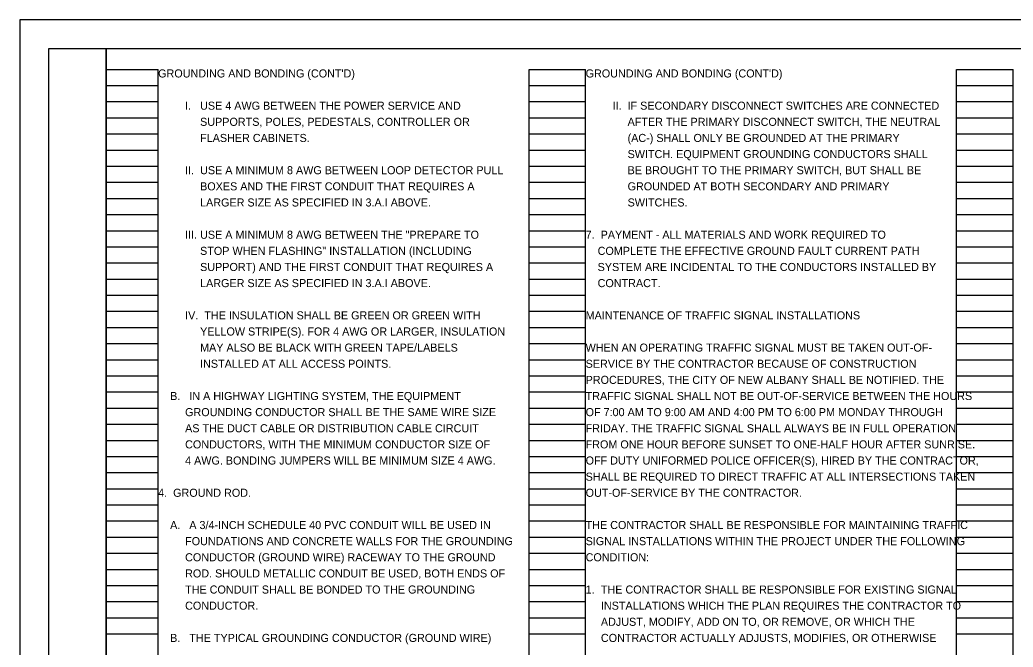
# Model space of a CAD drawing. Extents: x 0 to 34, y 0 to 22.
# Drawn here: x 0 to 17.24, y 11.11 to 22 of the extents above; entities that cross this region are included whole.
import ezdxf

# ---------------------------------------------------------------- set-up
doc = ezdxf.new("R2010")
doc.units = 0
for name, color, linetype in [('SH_Border', 7, 'Continuous'), ('SH_Cut_Line', 7, 'Continuous'), ('SH_Data', 7, 'Continuous'), ('SH_Text', 7, 'Continuous')]:
    doc.layers.add(name, color=color, linetype=linetype)

msp = doc.modelspace()

# ---------------------------------------------------------------- linework, layer by layer
at = {"layer": 'SH_Border'}
for points in [[(0.5, 21.5), (1.5, 21.5), (1.5, 0.5), (0.5, 0.5)], [(1.5, 21.5), (33.5, 21.5), (33.5, 0.5), (1.5, 0.5)]]:
    msp.add_lwpolyline(points, close=True, dxfattribs=at)
at = {"layer": 'SH_Cut_Line'}
msp.add_lwpolyline([(0, 0), (34, 0), (34, 22), (0, 22)], close=True, dxfattribs=at)
at = {"layer": 'SH_Data'}
for p, q in [((1.5, 0.98), (1.5, 21.14)), ((1.5, 21.14), (2.4, 21.14)), ((2.4, 0.98), (2.4, 21.14)), ((8.84, 0.98), (8.84, 21.14)), ((8.84, 21.14), (9.82, 21.14)), ((9.82, 0.98), (9.82, 21.14)), ((16.26, 0.98), (16.26, 21.14)), ((16.26, 21.14), (17.24, 21.14)), ((17.24, 0.98), (17.24, 21.14)), ((1.5, 20.86), (2.4, 20.86)), ((8.84, 20.86), (9.82, 20.86)), ((16.26, 20.86), (17.24, 20.86)), ((1.5, 20.58), (2.4, 20.58)), ((8.84, 20.58), (9.82, 20.58)), ((16.26, 20.58), (17.24, 20.58)), ((1.5, 20.3), (2.4, 20.3)), ((8.84, 20.3), (9.82, 20.3)), ((16.26, 20.3), (17.24, 20.3)), ((1.5, 20.02), (2.4, 20.02)), ((8.84, 20.02), (9.82, 20.02)), ((16.26, 20.02), (17.24, 20.02)), ((1.5, 19.74), (2.4, 19.74)), ((8.84, 19.74), (9.82, 19.74)), ((16.26, 19.74), (17.24, 19.74)), ((1.5, 19.46), (2.4, 19.46)), ((8.84, 19.46), (9.82, 19.46)), ((16.26, 19.46), (17.24, 19.46)), ((1.5, 19.18), (2.4, 19.18)), ((8.84, 19.18), (9.82, 19.18)), ((16.26, 19.18), (17.24, 19.18)), ((1.5, 18.9), (2.4, 18.9)), ((8.84, 18.9), (9.82, 18.9)), ((16.26, 18.9), (17.24, 18.9)), ((1.5, 18.62), (2.4, 18.62)), ((8.84, 18.62), (9.82, 18.62)), ((16.26, 18.62), (17.24, 18.62)), ((1.5, 18.34), (2.4, 18.34)), ((8.84, 18.34), (9.82, 18.34)), ((16.26, 18.34), (17.24, 18.34)), ((1.5, 18.06), (2.4, 18.06)), ((8.84, 18.06), (9.82, 18.06)), ((16.26, 18.06), (17.24, 18.06)), ((1.5, 17.78), (2.4, 17.78)), ((8.84, 17.78), (9.82, 17.78)), ((16.26, 17.78), (17.24, 17.78)), ((1.5, 17.5), (2.4, 17.5)), ((8.84, 17.5), (9.82, 17.5)), ((16.26, 17.5), (17.24, 17.5)), ((1.5, 17.22), (2.4, 17.22)), ((8.84, 17.22), (9.82, 17.22)), ((16.26, 17.22), (17.24, 17.22)), ((1.5, 16.94), (2.4, 16.94)), ((8.84, 16.94), (9.82, 16.94)), ((16.26, 16.94), (17.24, 16.94)), ((1.5, 16.66), (2.4, 16.66)), ((8.84, 16.66), (9.82, 16.66)), ((16.26, 16.66), (17.24, 16.66)), ((1.5, 16.38), (2.4, 16.38)), ((8.84, 16.38), (9.82, 16.38)), ((16.26, 16.38), (17.24, 16.38)), ((1.5, 16.1), (2.4, 16.1)), ((8.84, 16.1), (9.82, 16.1)), ((16.26, 16.1), (17.24, 16.1)), ((1.5, 15.82), (2.4, 15.82)), ((8.84, 15.82), (9.82, 15.82)), ((16.26, 15.82), (17.24, 15.82)), ((1.5, 15.54), (2.4, 15.54)), ((8.84, 15.54), (9.82, 15.54)), ((16.26, 15.54), (17.24, 15.54)), ((1.5, 15.26), (2.4, 15.26)), ((8.84, 15.26), (9.82, 15.26)), ((16.26, 15.26), (17.24, 15.26)), ((1.5, 14.98), (2.4, 14.98)), ((8.84, 14.98), (9.82, 14.98)), ((16.26, 14.98), (17.24, 14.98)), ((1.5, 14.7), (2.4, 14.7)), ((8.84, 14.7), (9.82, 14.7)), ((16.26, 14.7), (17.24, 14.7)), ((1.5, 14.42), (2.4, 14.42)), ((8.84, 14.42), (9.82, 14.42)), ((16.26, 14.42), (17.24, 14.42)), ((1.5, 14.14), (2.4, 14.14)), ((8.84, 14.14), (9.82, 14.14)), ((16.26, 14.14), (17.24, 14.14)), ((1.5, 13.86), (2.4, 13.86)), ((8.84, 13.86), (9.82, 13.86)), ((16.26, 13.86), (17.24, 13.86)), ((1.5, 13.58), (2.4, 13.58)), ((8.84, 13.58), (9.82, 13.58)), ((16.26, 13.58), (17.24, 13.58)), ((1.5, 13.3), (2.4, 13.3)), ((8.84, 13.3), (9.82, 13.3)), ((16.26, 13.3), (17.24, 13.3)), ((1.5, 13.02), (2.4, 13.02)), ((8.84, 13.02), (9.82, 13.02)), ((16.26, 13.02), (17.24, 13.02)), ((1.5, 12.74), (2.4, 12.74)), ((8.84, 12.74), (9.82, 12.74)), ((16.26, 12.74), (17.24, 12.74)), ((1.5, 12.46), (2.4, 12.46)), ((8.84, 12.46), (9.82, 12.46)), ((16.26, 12.46), (17.24, 12.46)), ((1.5, 12.18), (2.4, 12.18)), ((8.84, 12.18), (9.82, 12.18)), ((16.26, 12.18), (17.24, 12.18)), ((1.5, 11.9), (2.4, 11.9)), ((8.84, 11.9), (9.82, 11.9)), ((16.26, 11.9), (17.24, 11.9)), ((1.5, 11.62), (2.4, 11.62)), ((8.84, 11.62), (9.82, 11.62)), ((16.26, 11.62), (17.24, 11.62)), ((1.5, 11.34), (2.4, 11.34)), ((8.84, 11.34), (9.82, 11.34)), ((16.26, 11.34), (17.24, 11.34))]:
    msp.add_line(p, q, dxfattribs=at)

# ---------------------------------------------------------------- texts
at = {"layer": 'SH_Text'}
for s, p in [("GROUNDING AND BONDING (CONT'D)", (2.4, 21)), ("GROUNDING AND BONDING (CONT'D)", (9.82, 21)), ('         I.   USE 4 AWG BETWEEN THE POWER SERVICE AND', (2.4, 20.44)), ('         II.  IF SECONDARY DISCONNECT SWITCHES ARE CONNECTED', (9.82, 20.44)), ('              SUPPORTS, POLES, PEDESTALS, CONTROLLER OR', (2.4, 20.16)), ('              AFTER THE PRIMARY DISCONNECT SWITCH, THE NEUTRAL', (9.82, 20.16)), ('              FLASHER CABINETS.', (2.4, 19.88)), ('              (AC-) SHALL ONLY BE GROUNDED AT THE PRIMARY', (9.82, 19.88)), ('              SWITCH. EQUIPMENT GROUNDING CONDUCTORS SHALL', (9.82, 19.6)), ('         II.  USE A MINIMUM 8 AWG BETWEEN LOOP DETECTOR PULL', (2.4, 19.32)), ('              BE BROUGHT TO THE PRIMARY SWITCH, BUT SHALL BE', (9.82, 19.32)), ('              BOXES AND THE FIRST CONDUIT THAT REQUIRES A', (2.4, 19.04)), ('              GROUNDED AT BOTH SECONDARY AND PRIMARY', (9.82, 19.04)), ('              LARGER SIZE AS SPECIFIED IN 3.A.I ABOVE.', (2.4, 18.76)), ('              SWITCHES.', (9.82, 18.76)), ('         III. USE A MINIMUM 8 AWG BETWEEN THE "PREPARE TO', (2.4, 18.2)), ('7.  PAYMENT - ALL MATERIALS AND WORK REQUIRED TO', (9.82, 18.2)), ('              STOP WHEN FLASHING" INSTALLATION (INCLUDING', (2.4, 17.92)), ('    COMPLETE THE EFFECTIVE GROUND FAULT CURRENT PATH', (9.82, 17.92)), ('              SUPPORT) AND THE FIRST CONDUIT THAT REQUIRES A', (2.4, 17.64)), ('    SYSTEM ARE INCIDENTAL TO THE CONDUCTORS INSTALLED BY', (9.82, 17.64)), ('              LARGER SIZE AS SPECIFIED IN 3.A.I ABOVE.', (2.4, 17.36)), ('    CONTRACT.', (9.82, 17.36)), ('         IV.  THE INSULATION SHALL BE GREEN OR GREEN WITH', (2.4, 16.8)), ('MAINTENANCE OF TRAFFIC SIGNAL INSTALLATIONS', (9.82, 16.8)), ('              YELLOW STRIPE(S). FOR 4 AWG OR LARGER, INSULATION', (2.4, 16.52)), ('              MAY ALSO BE BLACK WITH GREEN TAPE/LABELS', (2.4, 16.24)), ('WHEN AN OPERATING TRAFFIC SIGNAL MUST BE TAKEN OUT-OF-', (9.82, 16.24)), ('              INSTALLED AT ALL ACCESS POINTS.', (2.4, 15.96)), ('SERVICE BY THE CONTRACTOR BECAUSE OF CONSTRUCTION ', (9.82, 15.96)), ('PROCEDURES, THE CITY OF NEW ALBANY SHALL BE NOTIFIED. THE ', (9.82, 15.68)), ('    B.   IN A HIGHWAY LIGHTING SYSTEM, THE EQUIPMENT', (2.4, 15.4)), ('TRAFFIC SIGNAL SHALL NOT BE OUT-OF-SERVICE BETWEEN THE HOURS ', (9.82, 15.4)), ('         GROUNDING CONDUCTOR SHALL BE THE SAME WIRE SIZE', (2.4, 15.12)), ('OF 7:00 AM TO 9:00 AM AND 4:00 PM TO 6:00 PM MONDAY THROUGH ', (9.82, 15.12)), ('         AS THE DUCT CABLE OR DISTRIBUTION CABLE CIRCUIT', (2.4, 14.84)), ('FRIDAY. THE TRAFFIC SIGNAL SHALL ALWAYS BE IN FULL OPERATION ', (9.82, 14.84)), ('         CONDUCTORS, WITH THE MINIMUM CONDUCTOR SIZE OF', (2.4, 14.56)), ('FROM ONE HOUR BEFORE SUNSET TO ONE-HALF HOUR AFTER SUNRISE. ', (9.82, 14.56)), ('         4 AWG. BONDING JUMPERS WILL BE MINIMUM SIZE 4 AWG.', (2.4, 14.28)), ('OFF DUTY UNIFORMED POLICE OFFICER(S), HIRED BY THE CONTRACTOR, ', (9.82, 14.28)), ('SHALL BE REQUIRED TO DIRECT TRAFFIC AT ALL INTERSECTIONS TAKEN ', (9.82, 14)), ('4.  GROUND ROD.', (2.4, 13.72)), ('OUT-OF-SERVICE BY THE CONTRACTOR.', (9.82, 13.72)), ('    A.   A 3/4-INCH SCHEDULE 40 PVC CONDUIT WILL BE USED IN', (2.4, 13.16)), ('THE CONTRACTOR SHALL BE RESPONSIBLE FOR MAINTAINING TRAFFIC ', (9.82, 13.16)), ('         FOUNDATIONS AND CONCRETE WALLS FOR THE GROUNDING', (2.4, 12.88)), ('SIGNAL INSTALLATIONS WITHIN THE PROJECT UNDER THE FOLLOWING ', (9.82, 12.88)), ('         CONDUCTOR (GROUND WIRE) RACEWAY TO THE GROUND', (2.4, 12.6)), ('CONDITION:', (9.82, 12.6)), ('         ROD. SHOULD METALLIC CONDUIT BE USED, BOTH ENDS OF', (2.4, 12.32)), ('         THE CONDUIT SHALL BE BONDED TO THE GROUNDING', (2.4, 12.04)), ('1.', (9.82, 12.04)), ('THE CONTRACTOR SHALL BE RESPONSIBLE FOR EXISTING SIGNAL ', (10.085, 12.04)), ('         CONDUCTOR.', (2.4, 11.76)), ('INSTALLATIONS WHICH THE PLAN REQUIRES THE CONTRACTOR TO ', (10.085, 11.76)), ('ADJUST, MODIFY, ADD ON TO, OR REMOVE, OR WHICH THE ', (10.085, 11.48)), ('    B.   THE TYPICAL GROUNDING CONDUCTOR (GROUND WIRE)', (2.4, 11.2)), ('CONTRACTOR ACTUALLY ADJUSTS, MODIFIES, OR OTHERWISE ', (10.085, 11.2))]:
    msp.add_text(s, height=0.14, dxfattribs=at).set_placement(p)

doc.saveas('drawing.dxf')
